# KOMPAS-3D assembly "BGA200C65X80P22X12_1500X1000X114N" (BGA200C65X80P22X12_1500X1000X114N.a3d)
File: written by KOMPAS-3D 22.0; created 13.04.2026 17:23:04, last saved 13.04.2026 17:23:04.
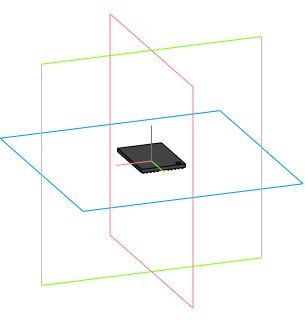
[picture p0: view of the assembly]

Document properties: Автор: Andrey; Полное имя файла: C:\Users\User1\Documents\BGA200C65X80P22X12_1500X1000X114N.a3d

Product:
- Component [detail]: MT53E1G32D2FW-046 AUT_B  | qty 1  | source file: MT53E1G32D2FW-046 AUT_B.m3d
- Part/product: BGA200C65X80P22X12_1500X1000X114N
    Комментарий: BGA200C65X80P22X12_1500X1000X114N

Referenced files in C:\Users\User1\Documents\: MT53E1G32D2FW-046 AUT_B.m3d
